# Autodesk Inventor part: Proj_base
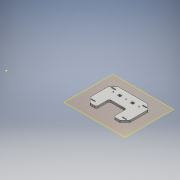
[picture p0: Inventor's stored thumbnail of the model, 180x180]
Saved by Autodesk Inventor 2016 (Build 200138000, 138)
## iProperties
Created: 2015-11
Part Number: Proj_base
Material: Generic
Document SubType Name: Modeling
Designer: John
Density: 1 g/cm^3
Appearance: Default
Author: John
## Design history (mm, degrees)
workplane "Work Plane1"
sketch "Sketch1"
  geometry: L1 (78.45, 44.2)-(78.45, -44.2) reference; L2 (63.45, -59.2)-(-63.45, -59.2) reference; L3 (-78.45, -44.2)-(-78.45, 44.2) reference; L4 (-63.45, 59.2)-(63.45, 59.2) reference; L5 (-161.15, -69.113)-(-161.15, -114.2) reference; L6 (-146.15, -129.2)-(-94.113, -129.2) reference; L7 (-83.507, -124.807)-(-66.893, -108.193) reference; L8 (-56.287, -103.8)-(56.287, -103.8) reference; L9 (66.893, -108.193)-(83.507, -124.807) reference; L10 (94.113, -129.2)-(146.15, -129.2) reference; L11 (161.15, -114.2)-(161.15, -69.113) reference; L12 (156.757, -58.507)-(140.143, -41.893) reference; L13 (135.75, -31.287)-(135.75, 31.287) reference; L14 (140.143, 41.893)-(156.757, 58.507) reference; L15 (161.15, 69.113)-(161.15, 114.2) reference; L16 (146.15, 129.2)-(94.113, 129.2) reference; L17 (83.507, 124.807)-(66.893, 108.193) reference; L18 (56.287, 103.8)-(-56.287, 103.8) reference; L19 (-66.893, 108.193)-(-83.507, 124.807) reference; L20 (-94.113, 129.2)-(-146.15, 129.2) reference; L21 (-161.15, 114.2)-(-161.15, 69.113) reference; L22 (-156.757, 58.507)-(-140.143, 41.893) reference; L23 (-135.75, 31.287)-(-135.75, -31.287) reference; L24 (-140.143, -41.893)-(-156.757, -58.507) reference; L25 (-93.775, 49.2)-(-93.775, 69.2) reference; L26 (-88.525, 69.2)-(-88.525, 49.2) reference; L27 (88.525, -69.2)-(88.525, -49.2) reference; L28 (93.775, -49.2)-(93.775, -69.2) reference; L29 (88.525, 49.2)-(88.525, 69.2) reference; L30 (93.775, 69.2)-(93.775, 49.2) reference; L31 (-93.775, -69.2)-(-93.775, -49.2) reference; L32 (-88.525, -49.2)-(-88.525, -69.2) reference; L33 (-116.55, 81.9)-(116.55, 81.9); L34 (116.55, 81.9)-(116.55, -81.9); L35 (116.55, -81.9)-(-116.55, -81.9); L36 (-116.55, -81.9)-(-116.55, 81.9); C1 r 19.5 at (-128.95, -97) reference; C2 r 19.5 at (-128.95, 97) reference; C3 r 19.5 at (128.95, 97) reference; C4 r 19.5 at (128.95, -97) reference; A1 r 15 centre (63.45, -44.2) between (63.45, -59.2) and (78.45, -44.2) reference; A2 r 15 centre (-63.45, -44.2) between (-78.45, -44.2) and (-63.45, -59.2) reference; A3 r 15 centre (-63.45, 44.2) between (-63.45, 59.2) and (-78.45, 44.2) reference; A4 r 15 centre (63.45, 44.2) between (78.45, 44.2) and (63.45, 59.2) reference; A5 r 15 centre (-146.15, -69.113) between (-156.757, -58.507) and (-161.15, -69.113) reference; A6 r 15 centre (-146.15, -114.2) between (-161.15, -114.2) and (-146.15, -129.2) reference; A7 r 15 centre (-94.113, -114.2) between (-94.113, -129.2) and (-83.507, -124.807) reference; A8 r 15 centre (-56.287, -118.8) between (-56.287, -103.8) and (-66.893, -108.193) reference; A9 r 15 centre (56.287, -118.8) between (66.893, -108.193) and (56.287, -103.8) reference; A10 r 15 centre (94.113, -114.2) between (83.507, -124.807) and (94.113, -129.2) reference; A11 r 15 centre (146.15, -114.2) between (146.15, -129.2) and (161.15, -114.2) reference; A12 r 15 centre (146.15, -69.113) between (161.15, -69.113) and (156.757, -58.507) reference; A13 r 15 centre (150.75, -31.287) between (135.75, -31.287) and (140.143, -41.893) reference; A14 r 15 centre (150.75, 31.287) between (140.143, 41.893) and (135.75, 31.287) reference; A15 r 15 centre (146.15, 69.113) between (156.757, 58.507) and (161.15, 69.113) reference; A16 r 15 centre (146.15, 114.2) between (161.15, 114.2) and (146.15, 129.2) reference; A17 r 15 centre (94.113, 114.2) between (94.113, 129.2) and (83.507, 124.807) reference; A18 r 15 centre (56.287, 118.8) between (56.287, 103.8) and (66.893, 108.193) reference; A19 r 15 centre (-56.287, 118.8) between (-66.893, 108.193) and (-56.287, 103.8) reference; A20 r 15 centre (-94.113, 114.2) between (-83.507, 124.807) and (-94.113, 129.2) reference; A21 r 15 centre (-146.15, 114.2) between (-146.15, 129.2) and (-161.15, 114.2) reference; A22 r 15 centre (-146.15, 69.113) between (-161.15, 69.113) and (-156.757, 58.507) reference; A23 r 15 centre (-150.75, 31.287) between (-135.75, 31.287) and (-140.143, 41.893) reference; A24 r 15 centre (-150.75, -31.287) between (-140.143, -41.893) and (-135.75, -31.287) reference; A25 r 2.625 centre (-91.15, 49.2) between (-93.775, 49.2) and (-88.525, 49.2) reference; A26 r 2.625 centre (-91.15, 69.2) between (-88.525, 69.2) and (-93.775, 69.2) reference; A27 r 2.625 centre (91.15, -69.2) between (88.525, -69.2) and (93.775, -69.2) reference; A28 r 2.625 centre (91.15, -49.2) between (93.775, -49.2) and (88.525, -49.2) reference; A29 r 2.625 centre (91.15, 49.2) between (88.525, 49.2) and (93.775, 49.2) reference; A30 r 2.625 centre (91.15, 69.2) between (93.775, 69.2) and (88.525, 69.2) reference; A31 r 2.625 centre (-91.15, -69.2) between (-93.775, -69.2) and (-88.525, -69.2) reference; A32 r 2.625 centre (-91.15, -49.2) between (-88.525, -49.2) and (-93.775, -49.2) reference; 1 further point
  constraints: 8 end point, 2 parallel, 1 horizontal, 1 perpendicular
  dimensions: "d0" = 12.7 distance from line of A26.centre L33; "d1" = 25.4 distance from line of A26.centre L36; "d2" = 25.4 distance from line of A30.centre L34 (= d1); "d3" = 12.7 distance from line of A27.centre L35 (= d0)
extrude "Extrusion1" new body sketch "Sketch1" distance "d4" = 12.7; taper "d5" = 0 deg
sketch "Sketch2"
  geometry: L1 (93.775, 69.2)-(93.775, 49.2) reference; L2 (88.525, 49.2)-(88.525, 69.2) reference; L3 (93.775, -49.2)-(93.775, -69.2) reference; L4 (88.525, -69.2)-(88.525, -49.2) reference; L5 (-88.525, -49.2)-(-88.525, -69.2) reference; L6 (-93.775, -69.2)-(-93.775, -49.2) reference; L7 (-88.525, 69.2)-(-88.525, 49.2) reference; L8 (-93.775, 49.2)-(-93.775, 69.2) reference; L9 (-101.15, 59.2)-(-81.15, 59.2); L10 (-101.15, 61.825)-(-81.15, 61.825); L11 (-81.15, 56.575)-(-101.15, 56.575); L12 (-101.15, -59.2)-(-81.15, -59.2); L13 (-101.15, -56.575)-(-81.15, -56.575); L14 (-81.15, -61.825)-(-101.15, -61.825); L15 (81.15, -59.2)-(101.15, -59.2); L16 (81.15, -56.575)-(101.15, -56.575); L17 (101.15, -61.825)-(81.15, -61.825); L18 (81.15, 59.2)-(101.15, 59.2); L19 (81.15, 56.575)-(101.15, 56.575); L20 (101.15, 61.825)-(81.15, 61.825); A1 r 2.625 centre (91.15, 69.2) between (93.775, 69.2) and (88.525, 69.2) reference; A2 r 2.625 centre (91.15, 49.2) between (88.525, 49.2) and (93.775, 49.2) reference; A3 r 2.625 centre (91.15, -69.2) between (88.525, -69.2) and (93.775, -69.2) reference; A4 r 2.625 centre (91.15, -49.2) between (93.775, -49.2) and (88.525, -49.2) reference; A5 r 2.625 centre (-91.15, -69.2) between (-93.775, -69.2) and (-88.525, -69.2) reference; A6 r 2.625 centre (-91.15, -49.2) between (-88.525, -49.2) and (-93.775, -49.2) reference; A7 r 2.625 centre (-91.15, 49.2) between (-93.775, 49.2) and (-88.525, 49.2) reference; A8 r 2.625 centre (-91.15, 69.2) between (-88.525, 69.2) and (-93.775, 69.2) reference; A9 r 2.625 centre (-101.15, 59.2) between (-101.15, 61.825) and (-101.15, 56.575); A10 r 2.625 centre (-81.15, 59.2) between (-81.15, 56.575) and (-81.15, 61.825); A11 r 2.625 centre (-101.15, -59.2) between (-101.15, -56.575) and (-101.15, -61.825); A12 r 2.625 centre (-81.15, -59.2) between (-81.15, -61.825) and (-81.15, -56.575); A13 r 2.625 centre (81.15, -59.2) between (81.15, -56.575) and (81.15, -61.825); A14 r 2.625 centre (101.15, -59.2) between (101.15, -61.825) and (101.15, -56.575); A15 r 2.625 centre (81.15, 59.2) between (81.15, 61.825) and (81.15, 56.575); A16 r 2.625 centre (101.15, 59.2) between (101.15, 56.575) and (101.15, 61.825); 5 further points
  constraints: 32 end point, 16 point on circle, 16 tangent, 8 centre point, 5 parallel, 4 equal length, 4 midpoint, 4 vertical alignment, 3 equal radius, 2 horizontal, 2 horizontal alignment, 2 point on line
  dimensions: "d7" = 5.25 distance between parallel lines of L10 L11; "d8" = 10 distance of A6.centre point (-91.15, -59.2); "d9" = 10 distance of A8.centre point (-91.15, 59.2) (= d8)
extrude "Extrusion2" cut sketch "Sketch2" stored distance "d10" = 12.7; taper "d11" = 0 deg
sketch "Sketch3"
  geometry: 1 further point
sketch "Sketch4"
  geometry: L1 (-101.15, 61.825)-(-81.15, 61.825) reference; L2 (-81.15, 56.575)-(-101.15, 56.575) reference; L3 (81.15, -56.575)-(101.15, -56.575) reference; L4 (101.15, -61.825)-(81.15, -61.825) reference; L5 (101.15, 56.575)-(81.15, 56.575) reference; L6 (81.15, 61.825)-(101.15, 61.825) reference; L7 (-101.15, -56.575)-(-81.15, -56.575) reference; L8 (-81.15, -61.825)-(-101.15, -61.825) reference; L9 (116.55, 81.9)-(-116.55, 81.9) reference; L10 (-116.55, 81.9)-(-116.55, -81.9) reference; L11 (-116.55, -81.9)-(116.55, -81.9) reference; L12 (116.55, -81.9)-(116.55, 81.9) reference; L13 (-45, 48.4)-(-30, 48.4); L14 (-30, 48.4)-(-30, 35.4); L15 (-30, 35.4)-(-45, 35.4); L16 (-45, 35.4)-(-45, 48.4); L17 (30, 48.4)-(45, 48.4); L18 (45, 48.4)-(45, 35.4); L19 (45, 35.4)-(30, 35.4); L20 (30, 35.4)-(30, 48.4); C1 r 2.625 at (0, 41.9); C2 r 2.625 at (75, 41.9); C3 r 2.625 at (-75, 41.9); A1 r 2.625 centre (-101.15, 59.2) between (-101.15, 61.825) and (-101.15, 56.575) reference; A2 r 2.625 centre (-81.15, 59.2) between (-81.15, 56.575) and (-81.15, 61.825) reference; A3 r 2.625 centre (81.15, -59.2) between (81.15, -56.575) and (81.15, -61.825) reference; A4 r 2.625 centre (101.15, -59.2) between (101.15, -61.825) and (101.15, -56.575) reference; A5 r 2.625 centre (101.15, 59.2) between (101.15, 56.575) and (101.15, 61.825) reference; A6 r 2.625 centre (81.15, 59.2) between (81.15, 61.825) and (81.15, 56.575) reference; A7 r 2.625 centre (-101.15, -59.2) between (-101.15, -56.575) and (-101.15, -61.825) reference; A8 r 2.625 centre (-81.15, -59.2) between (-81.15, -61.825) and (-81.15, -56.575) reference; 6 further points
  constraints: 16 end point, 5 midpoint, 4 horizontal alignment, 4 parallel, 3 centre point, 2 equal radius, 2 horizontal, 2 perpendicular, 2 point on line, 1 collinear, 1 vertical alignment
  dimensions: "d12" = 30 distance from line of C1.centre L14; "d13" = 5.25 diameter of C1; "d14" = 30 distance from line of L16 C3.centre (= d12); "d15" = 30 distance of point (45, 41.9) C2.centre (= d12); "d16" = 30 distance from line of C1.centre L20 (= d12); "d17" = 13 distance between parallel lines of L15 L13; "d18" = 15 distance of L14.end L15.end; "d19" = 40 distance from line of L9 C1.centre
extrude "Extrusion3" cut sketch "Sketch4" stored distance "d20" = 12.7; taper "d21" = 0 deg
sketch "Sketch5"
  geometry: L1 (-45, 35.4)-(-45, 48.4) reference; L2 (-45, 48.4)-(-30, 48.4) reference; L3 (-30, 48.4)-(-30, 35.4) reference; L4 (-30, 35.4)-(-45, 35.4) reference; L5 (30, 35.4)-(30, 48.4) reference; L6 (30, 48.4)-(45, 48.4) reference; L7 (45, 48.4)-(45, 35.4) reference; L8 (45, 35.4)-(30, 35.4) reference; L9 (-101.15, 61.825)-(-81.15, 61.825) reference; L10 (-81.15, 56.575)-(-101.15, 56.575) reference; L11 (81.15, -56.575)-(101.15, -56.575) reference; L12 (101.15, -61.825)-(81.15, -61.825) reference; L13 (101.15, 56.575)-(81.15, 56.575) reference; L14 (81.15, 61.825)-(101.15, 61.825) reference; L15 (-101.15, -56.575)-(-81.15, -56.575) reference; L16 (-81.15, -61.825)-(-101.15, -61.825) reference; L17 (116.55, 81.9)-(-116.55, 81.9) reference; L18 (-116.55, 81.9)-(-116.55, -81.9) reference; L19 (-116.55, -81.9)-(116.55, -81.9) reference; L20 (116.55, -81.9)-(116.55, 81.9) reference; L21 (-50, -81.9)-(50, -81.9); L22 (50, -81.9)-(50, -6.9); L23 (50, -6.9)-(-50, -6.9); L24 (-50, -6.9)-(-50, -81.9); C1 r 2.625 at (75, 41.9) reference; C2 r 2.625 at (0, 41.9) reference; C3 r 2.625 at (-75, 41.9) reference; A1 r 2.625 centre (-101.15, 59.2) between (-101.15, 61.825) and (-101.15, 56.575) reference; A2 r 2.625 centre (-81.15, 59.2) between (-81.15, 56.575) and (-81.15, 61.825) reference; A3 r 2.625 centre (81.15, -59.2) between (81.15, -56.575) and (81.15, -61.825) reference; A4 r 2.625 centre (101.15, -59.2) between (101.15, -61.825) and (101.15, -56.575) reference; A5 r 2.625 centre (101.15, 59.2) between (101.15, 56.575) and (101.15, 61.825) reference; A6 r 2.625 centre (81.15, 59.2) between (81.15, 61.825) and (81.15, 56.575) reference; A7 r 2.625 centre (-101.15, -59.2) between (-101.15, -56.575) and (-101.15, -61.825) reference; A8 r 2.625 centre (-81.15, -59.2) between (-81.15, -61.825) and (-81.15, -56.575) reference; 2 further points
  constraints: 8 end point, 2 midpoint, 2 parallel, 1 horizontal, 1 perpendicular, 1 point on line
  dimensions: "d22" = 100 distance of L22.end L23.end; "d23" = 75 distance of L21.end L22.end
extrude "Extrusion4" cut sketch "Sketch5" distance "d24" = 12.7; taper "d25" = 0 deg
fillet "Fillet2" dims "d26" = 10
chamfer "Chamfer1" distance "d27" = 30; stored, may be unused: second distance "d28" = 2, angle "d29" = 45 deg
fillet "Fillet3" dims "d30" = 10
body "Solid1"
node "Reference1"
node "Projected Loop1"
node "Projected Loop2"
